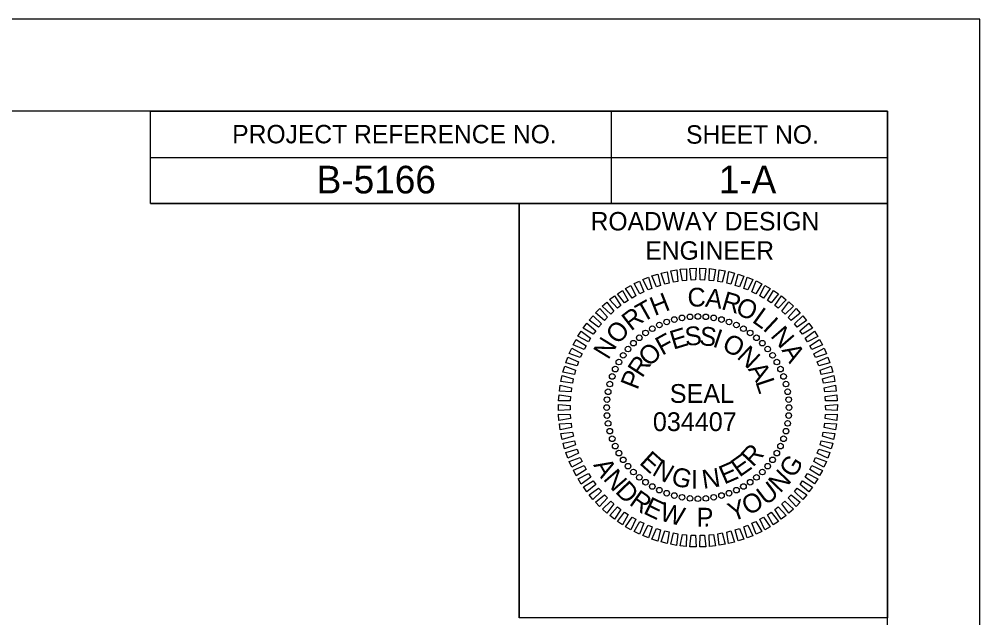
# Model space of a CAD drawing. Extents: x 972 to 1006, y 10585.8 to 10607.8.
# Drawn here: x 1000.77 to 1005.99, y 10604.53 to 10607.78 of the extents above; entities that cross this region are included whole.
import ezdxf

# ---------------------------------------------------------------- set-up
doc = ezdxf.new("R2010")
doc.units = 0
for name, color, linetype in [('Sheet Data Field CELL', 7, 'Continuous'), ('Sheet PE Seal Cell', 7, 'Continuous'), ('Sheet Plan CELL', 7, 'Continuous'), ('Stewart Plot Border Xerox6279 and LJ5000', 7, 'Continuous')]:
    doc.layers.add(name, color=color, linetype=linetype)

msp = doc.modelspace()

# ---------------------------------------------------------------- linework, layer by layer
at = {"layer": 'Sheet PE Seal Cell'}
for points in [[(1004.232, 10606.3315), (1004.2078, 10606.3904), (1004.2393, 10606.4), (1004.2541, 10606.3389)], [(1004.2783, 10606.3456), (1004.2582, 10606.4061), (1004.2904, 10606.4135), (1004.3009, 10606.3514)], [(1004.3255, 10606.3565), (1004.3097, 10606.4182), (1004.3422, 10606.4233), (1004.3484, 10606.3607)], [(1004.3733, 10606.364), (1004.3618, 10606.4267), (1004.3947, 10606.4295), (1004.3964, 10606.3666)], [(1004.4215, 10606.3682), (1004.4144, 10606.4315), (1004.4474, 10606.4321), (1004.4448, 10606.3692)], [(1004.4699, 10606.369), (1004.4673, 10606.4326), (1004.5002, 10606.4309), (1004.4932, 10606.3684)], [(1004.5182, 10606.3665), (1004.5201, 10606.4301), (1004.5528, 10606.4261), (1004.5414, 10606.3642)], [(1004.5663, 10606.3605), (1004.5725, 10606.4239), (1004.6049, 10606.4176), (1004.5892, 10606.3566)], [(1004.6138, 10606.3513), (1004.6244, 10606.414), (1004.6563, 10606.4055), (1004.6364, 10606.3458)], [(1004.6605, 10606.3387), (1004.6755, 10606.4006), (1004.7067, 10606.3898), (1004.6827, 10606.3316)], [(1004.1429, 10606.2938), (1004.1107, 10606.3487), (1004.1406, 10606.3626), (1004.1638, 10606.3041)], [(1004.1868, 10606.3142), (1004.1585, 10606.3713), (1004.1893, 10606.3831), (1004.2083, 10606.3231)], [(1004.7063, 10606.3229), (1004.7256, 10606.3836), (1004.7559, 10606.3707), (1004.7279, 10606.3143)], [(1004.7508, 10606.304), (1004.7743, 10606.3631), (1004.8037, 10606.3482), (1004.7718, 10606.2939)], [(1004.0599, 10606.244), (1004.0204, 10606.2939), (1004.0481, 10606.3119), (1004.0792, 10606.2572)], [(1004.1006, 10606.2703), (1004.0646, 10606.3229), (1004.0935, 10606.3389), (1004.1207, 10606.2821)], [(1004.7939, 10606.282), (1004.8215, 10606.3394), (1004.8497, 10606.3224), (1004.8142, 10606.2704)], [(1004.8354, 10606.257), (1004.8669, 10606.3123), (1004.8939, 10606.2934), (1004.8548, 10606.2441)], [(1003.9847, 10606.1832), (1003.9386, 10606.2271), (1003.9635, 10606.2487), (1004.0019, 10606.1989)], [(1004.0213, 10606.2149), (1003.9784, 10606.262), (1004.0047, 10606.2818), (1004.0395, 10606.2294)], [(1004.875, 10606.2292), (1004.9103, 10606.2822), (1004.9359, 10606.2615), (1004.8935, 10606.215)], [(1004.9126, 10606.1987), (1004.9515, 10606.2491), (1004.9756, 10606.2266), (1004.9301, 10606.1832)], [(1003.9505, 10606.149), (1003.9014, 10606.1896), (1003.9248, 10606.2129), (1003.9665, 10606.1658)], [(1004.948, 10606.1657), (1004.9903, 10606.2133), (1005.0128, 10606.1891), (1004.9643, 10606.149)], [(1003.9187, 10606.1125), (1003.8669, 10606.1496), (1003.8886, 10606.1744), (1003.9335, 10606.1304)], [(1004.981, 10606.1303), (1005.0265, 10606.1748), (1005.0473, 10606.1491), (1004.9961, 10606.1125)], [(1003.8631, 10606.0332), (1003.8067, 10606.0628), (1003.8247, 10606.0904), (1003.8754, 10606.0531)], [(1003.8895, 10606.0738), (1003.8353, 10606.1072), (1003.8552, 10606.1335), (1003.9031, 10606.0928)], [(1005.0114, 10606.0926), (1005.06, 10606.1339), (1005.0789, 10606.1068), (1005.0253, 10606.0739)], [(1005.0392, 10606.053), (1005.0905, 10606.0907), (1005.1074, 10606.0624), (1005.0517, 10606.0333)], [(1003.8396, 10605.9909), (1003.7813, 10606.0165), (1003.7973, 10606.0453), (1003.8504, 10606.0116)], [(1005.0641, 10606.0115), (1005.1179, 10606.0455), (1005.1328, 10606.0161), (1005.0751, 10605.9909)], [(1003.8191, 10605.9471), (1003.7592, 10605.9685), (1003.7731, 10605.9984), (1003.8285, 10605.9684)], [(1005.086, 10605.9683), (1005.1421, 10605.9985), (1005.1549, 10605.9682), (1005.0956, 10605.9471)], [(1003.8018, 10605.9019), (1003.7405, 10605.9191), (1003.7523, 10605.9498), (1003.8096, 10605.9238)], [(1005.1049, 10605.9237), (1005.1629, 10605.95), (1005.1736, 10605.9188), (1005.113, 10605.9019)], [(1003.7876, 10605.8556), (1003.7252, 10605.8685), (1003.7349, 10605.9), (1003.7939, 10605.8781)], [(1005.1206, 10605.878), (1005.1803, 10605.9001), (1005.1888, 10605.8683), (1005.1272, 10605.8556)], [(1003.7767, 10605.8085), (1003.7136, 10605.8169), (1003.721, 10605.8491), (1003.7814, 10605.8313)], [(1005.1331, 10605.8312), (1005.1942, 10605.8491), (1005.2005, 10605.8168), (1005.1381, 10605.8084)], [(1003.7691, 10605.7606), (1003.7055, 10605.7647), (1003.7107, 10605.7973), (1003.7722, 10605.7837)], [(1005.1423, 10605.7837), (1005.2045, 10605.7973), (1005.2085, 10605.7646), (1005.1457, 10605.7606)], [(1003.7648, 10605.7124), (1003.7011, 10605.712), (1003.704, 10605.7449), (1003.7663, 10605.7357)], [(1005.1482, 10605.7356), (1005.2112, 10605.7449), (1005.2129, 10605.7119), (1005.15, 10605.7124)], [(1003.7639, 10605.664), (1003.7004, 10605.6592), (1003.701, 10605.6922), (1003.7638, 10605.6873)], [(1005.1507, 10605.6873), (1005.2142, 10605.6921), (1005.2136, 10605.6592), (1005.1508, 10605.664)], [(1003.7664, 10605.6157), (1003.7034, 10605.6064), (1003.7017, 10605.6394), (1003.7647, 10605.6389)], [(1005.1498, 10605.6389), (1005.2135, 10605.6393), (1005.2106, 10605.6064), (1005.1483, 10605.6156)], [(1003.7723, 10605.5676), (1003.7101, 10605.554), (1003.7061, 10605.5868), (1003.7689, 10605.5907)], [(1005.1456, 10605.5907), (1005.2091, 10605.5866), (1005.2039, 10605.5541), (1005.1425, 10605.5676)], [(1003.7815, 10605.5201), (1003.7204, 10605.5022), (1003.7141, 10605.5346), (1003.7765, 10605.5429)], [(1005.138, 10605.5429), (1005.2011, 10605.5344), (1005.1936, 10605.5023), (1005.1333, 10605.52)], [(1003.794, 10605.4734), (1003.7343, 10605.4512), (1003.7258, 10605.4831), (1003.7874, 10605.4957)], [(1005.127, 10605.4957), (1005.1894, 10605.4829), (1005.1797, 10605.4513), (1005.1208, 10605.4733)], [(1003.8097, 10605.4276), (1003.7517, 10605.4013), (1003.741, 10605.4325), (1003.8016, 10605.4494)], [(1005.1129, 10605.4494), (1005.1742, 10605.4323), (1005.1623, 10605.4015), (1005.105, 10605.4275)], [(1003.8286, 10605.383), (1003.7726, 10605.3528), (1003.7597, 10605.3831), (1003.819, 10605.4042)], [(1003.8506, 10605.3399), (1003.7968, 10605.3058), (1003.7818, 10605.3352), (1003.8395, 10605.3604)], [(1005.075, 10605.3604), (1005.1333, 10605.3349), (1005.1173, 10605.306), (1005.0642, 10605.3398)], [(1005.0955, 10605.4043), (1005.1554, 10605.3829), (1005.1415, 10605.353), (1005.0861, 10605.3829)], [(1003.8755, 10605.2984), (1003.8242, 10605.2606), (1003.8072, 10605.2889), (1003.863, 10605.3181)], [(1005.0515, 10605.3181), (1005.1079, 10605.2885), (1005.0899, 10605.2609), (1005.0393, 10605.2982)], [(1003.9032, 10605.2587), (1003.8547, 10605.2175), (1003.8358, 10605.2445), (1003.8894, 10605.2775)], [(1005.0251, 10605.2775), (1005.0793, 10605.2441), (1005.0595, 10605.2178), (1005.0115, 10605.2586)], [(1003.9336, 10605.2211), (1003.8881, 10605.1765), (1003.8674, 10605.2022), (1003.9185, 10605.2388)], [(1003.9666, 10605.1856), (1003.9243, 10605.1381), (1003.9018, 10605.1622), (1003.9503, 10605.2023)], [(1004.9642, 10605.2024), (1005.0132, 10605.1617), (1004.9899, 10605.1384), (1004.9481, 10605.1855)], [(1004.9959, 10605.2389), (1005.0477, 10605.2018), (1005.026, 10605.1769), (1004.9811, 10605.2209)], [(1004.002, 10605.1526), (1003.9631, 10605.1022), (1003.939, 10605.1247), (1003.9846, 10605.1681)], [(1004.9299, 10605.1682), (1004.976, 10605.1242), (1004.9511, 10605.1026), (1004.9127, 10605.1525)], [(1004.0396, 10605.1221), (1004.0043, 10605.0691), (1003.9787, 10605.0899), (1004.0211, 10605.1363)], [(1004.0792, 10605.0943), (1004.0477, 10605.039), (1004.0207, 10605.0579), (1004.0598, 10605.1072)], [(1004.8547, 10605.1073), (1004.8942, 10605.0574), (1004.8665, 10605.0394), (1004.8354, 10605.0942)], [(1004.8934, 10605.1364), (1004.9363, 10605.0894), (1004.9099, 10605.0695), (1004.8751, 10605.122)], [(1004.1207, 10605.0694), (1004.0931, 10605.012), (1004.0649, 10605.029), (1004.1004, 10605.0809)], [(1004.1638, 10605.0474), (1004.1403, 10604.9882), (1004.1109, 10605.0032), (1004.1428, 10605.0574)], [(1004.7717, 10605.0576), (1004.8039, 10605.0026), (1004.774, 10604.9887), (1004.7508, 10605.0472)], [(1004.8141, 10605.081), (1004.85, 10605.0284), (1004.8212, 10605.0125), (1004.794, 10605.0692)], [(1004.2084, 10605.0284), (1004.189, 10604.9677), (1004.1587, 10604.9806), (1004.1867, 10605.037)], [(1004.2541, 10605.0126), (1004.2391, 10604.9508), (1004.2079, 10604.9615), (1004.2319, 10605.0197)], [(1004.3009, 10605.0001), (1004.2902, 10604.9373), (1004.2583, 10604.9458), (1004.2782, 10605.0056)], [(1004.3484, 10604.9908), (1004.3421, 10604.9274), (1004.3097, 10604.9337), (1004.3254, 10604.9947)], [(1004.5892, 10604.9948), (1004.605, 10604.9332), (1004.5724, 10604.928), (1004.5662, 10604.9906)], [(1004.6363, 10605.0057), (1004.6564, 10604.9453), (1004.6243, 10604.9379), (1004.6138, 10604.9999)], [(1004.6826, 10605.0198), (1004.7069, 10604.9609), (1004.6753, 10604.9513), (1004.6605, 10605.0125)], [(1004.7278, 10605.0371), (1004.7561, 10604.9801), (1004.7253, 10604.9683), (1004.7063, 10605.0283)], [(1004.3964, 10604.9849), (1004.3946, 10604.9212), (1004.3618, 10604.9253), (1004.3732, 10604.9872)], [(1004.4447, 10604.9823), (1004.4473, 10604.9187), (1004.4144, 10604.9204), (1004.4214, 10604.983)], [(1004.4931, 10604.9831), (1004.5002, 10604.9198), (1004.4672, 10604.9193), (1004.4698, 10604.9821)], [(1004.5414, 10604.9873), (1004.5528, 10604.9247), (1004.5199, 10604.9218), (1004.5182, 10604.9847)]]:
    msp.add_lwpolyline(points, close=True, dxfattribs=at)
for centre in [(1004.2482, 10606.1241), (1004.2881, 10606.1406), (1004.3293, 10606.1536), (1004.3714, 10606.1629), (1004.4142, 10606.1685), (1004.4573, 10606.1704), (1004.5004, 10606.1685), (1004.5432, 10606.1629), (1004.5854, 10606.1536), (1004.6265, 10606.1406), (1004.6664, 10606.1241), (1004.1735, 10606.0809), (1004.2099, 10606.1041), (1004.7047, 10606.1041), (1004.7411, 10606.0809), (1004.1075, 10606.0255), (1004.1393, 10606.0547), (1004.7753, 10606.0547), (1004.8072, 10606.0255), (1004.0783, 10605.9937), (1004.8363, 10605.9937), (1004.0288, 10605.923), (1004.052, 10605.9594), (1004.8626, 10605.9594), (1004.8858, 10605.923), (1004.0089, 10605.8848), (1004.9057, 10605.8848), (1003.9924, 10605.8449), (1004.9222, 10605.8449), (1003.9701, 10605.7616), (1003.9794, 10605.8037), (1004.9352, 10605.8037), (1004.9445, 10605.7616), (1003.9644, 10605.7188), (1004.9502, 10605.7188), (1003.9626, 10605.6757), (1004.9521, 10605.6757), (1003.9644, 10605.6325), (1004.9502, 10605.6325), (1003.9701, 10605.5898), (1003.9794, 10605.5476), (1004.9352, 10605.5476), (1004.9445, 10605.5898), (1003.9924, 10605.5064), (1004.9222, 10605.5064), (1004.0089, 10605.4666), (1004.9057, 10605.4666), (1004.0288, 10605.4283), (1004.052, 10605.3919), (1004.8626, 10605.3919), (1004.8858, 10605.4283), (1004.0783, 10605.3576), (1004.8363, 10605.3576), (1004.1075, 10605.3258), (1004.1393, 10605.2967), (1004.7753, 10605.2967), (1004.8072, 10605.3258), (1004.1735, 10605.2704), (1004.2099, 10605.2472), (1004.7047, 10605.2472), (1004.7411, 10605.2704), (1004.2482, 10605.2273), (1004.2881, 10605.2108), (1004.3293, 10605.1978), (1004.3714, 10605.1884), (1004.4142, 10605.1828), (1004.5004, 10605.1828), (1004.5432, 10605.1884), (1004.5854, 10605.1978), (1004.6265, 10605.2108), (1004.6664, 10605.2273), (1004.4573, 10605.1809)]:
    msp.add_circle(centre, 0.0153, dxfattribs=at)
at = {"layer": 'Sheet Plan CELL'}
for p, q in [((1003.9871, 10607.2837), (1003.9871, 10606.7837)), ((1001.4861, 10607.0337), (1005.4871, 10607.0337)), ((1001.4861, 10606.7837), (1005.4871, 10606.7837)), ((1001.4861, 10606.7837), (1005.4871, 10606.7837)), ((1003.4871, 10606.7837), (1003.4871, 10604.5347))]:
    msp.add_line(p, q, dxfattribs=at)
for points in [[(1005.4871, 10607.2847), (975.4871, 10607.2847), (975.4871, 10586.2847), (1005.4871, 10586.2847)], [(1001.4861, 10607.2847), (1005.4871, 10607.2847), (1005.4871, 10606.7837), (1001.4861, 10606.7837)], [(1003.4871, 10606.7837), (1005.4871, 10606.7837), (1005.4871, 10604.5337), (1003.4871, 10604.5337)]]:
    msp.add_lwpolyline(points, close=True, dxfattribs=at)
at = {"layer": 'Stewart Plot Border Xerox6279 and LJ5000'}
msp.add_lwpolyline([(971.9871, 10585.7847), (1005.9871, 10585.7847), (1005.9871, 10607.7847), (971.9871, 10607.7847)], close=True, dxfattribs=at)

# ---------------------------------------------------------------- texts
at = {"layer": 'Sheet Data Field CELL'}
for s, p in [('B-5166', (1002.3887, 10606.8387)), ('1-A', (1004.5706, 10606.8397))]:
    msp.add_text(s, height=0.15, dxfattribs=at).set_placement(p)
at = {"layer": 'Sheet PE Seal Cell'}
for s, height, rotation, p in [('H', 0.102, 21.601, (1004.2223, 10606.1723)), ('C', 0.102, 1.9618, (1004.4029, 10606.2224)), ('A', 0.102, 352.4568, (1004.4939, 10606.2239)), ('R', 0.102, 343.4093, (1004.5797, 10606.2113)), ('T', 0.102, 29.3903, (1004.1571, 10606.1359)), ('O', 0.102, 335.2006, (1004.6549, 10606.1884)), ('R', 0.102, 37.5989, (1004.0945, 10606.0883)), ('L', 0.102, 324.4755, (1004.7468, 10606.1427)), ('O', 0.102, 48.3241, (1004.024, 10606.0136)), ('I', 0.102, 317.0103, (1004.8051, 10606.1011)), ('E', 0.102, 16.986, (1004.3241, 10605.9896)), ('S', 0.102, 5.2237, (1004.3909, 10606.0102)), ('S', 0.102, 353.2648, (1004.4616, 10606.0167)), ('I', 0.102, 341.3058, (1004.5322, 10606.0084)), ('N', 0.102, 311.0704, (1004.8472, 10606.0628)), ('N', 0.102, 58.5345, (1003.971, 10605.9314)), ('F', 0.102, 28.6639, (1004.2633, 10605.9562)), ('O', 0.102, 332.5504, (1004.582, 10605.9931)), ('O', 0.102, 44.4727, (1004.1942, 10605.8927)), ('N', 0.102, 316.7416, (1004.6638, 10605.9471)), ('A', 0.102, 300.8599, (1004.9097, 10605.9876)), ('R', 0.102, 56.5721, (1004.1546, 10605.8327)), ('P', 0.102, 68.3344, (1004.1289, 10605.7677)), ('A', 0.102, 301.6915, (1004.7272, 10605.8842)), ('L', 0.102, 288.3556, (1004.768, 10605.8164)), ('SEAL', 0.10201, 360, (1004.3048, 10605.7012)), ('034407', 0.10201, 360, (1004.213, 10605.5482)), ('R', 0.102, 47.043, (1004.7559, 10605.3489)), ('E', 0.102, 317.8506, (1004.1348, 10605.3725)), ('E', 0.102, 35.2807, (1004.683, 10605.2949)), ('G', 0.102, 57.5346, (1004.9777, 10605.2879)), ('A', 0.102, 300.1138, (1003.8879, 10605.3642)), ('N', 0.102, 329.6129, (1004.2033, 10605.3131)), ('E', 0.102, 23.5185, (1004.6006, 10605.2569)), ('N', 0.102, 310.9861, (1003.9397, 10605.2862)), ('G', 0.102, 344.6629, (1004.3062, 10605.2596)), ('I', 0.102, 359.713, (1004.4194, 10605.2347)), ('N', 0.102, 8.4684, (1004.487, 10605.234)), ('N', 0.102, 46.2089, (1004.9035, 10605.2071)), ('D', 0.102, 314.4857, (1004.0042, 10605.2162)), ('U', 0.102, 37.1614, (1004.8257, 10605.1414)), ('R', 0.102, 324.6007, (1004.0797, 10605.1514)), ('O', 0.102, 28.9527, (1004.7309, 10605.0872)), ('E', 0.102, 334.3044, (1004.1562, 10605.1026)), ('W', 0.102, 344.4659, (1004.2439, 10605.0652)), ('Y', 0.102, 19.4477, (1004.6423, 10605.0551)), ('P', 0.102, 0.1574, (1004.4508, 10605.0293)), ('.', 0.102, 3.4784, (1004.4873, 10605.0288))]:
    msp.add_text(s, height=height, rotation=rotation, dxfattribs=at).set_placement(p)
at = {"layer": 'Sheet Plan CELL'}
for s, height, p in [('PROJECT REFERENCE NO.', 0.100002, (1001.9301, 10607.1107)), ('SHEET NO.', 0.1, (1004.3931, 10607.1087)), ('ROADWAY DESIGN', 0.100002, (1003.8751, 10606.6377)), ('ENGINEER', 0.1, (1004.1721, 10606.4787))]:
    msp.add_text(s, height=height, dxfattribs=at).set_placement(p)

doc.saveas('drawing.dxf')
